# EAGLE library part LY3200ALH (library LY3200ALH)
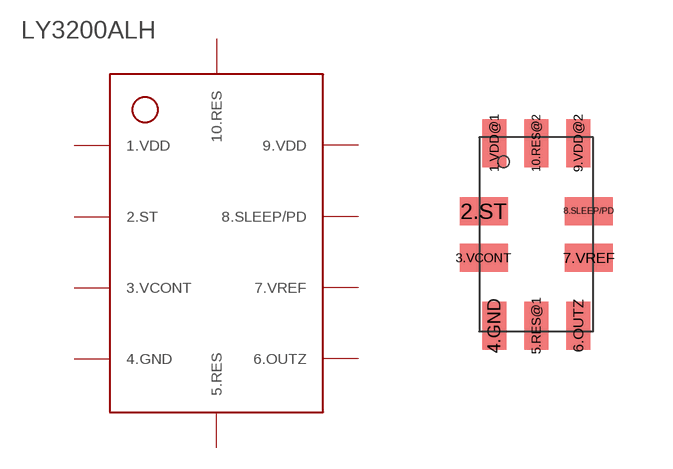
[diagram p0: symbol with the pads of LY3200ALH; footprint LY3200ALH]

Designator prefix -

## LY3200ALH  [LY3200ALH]
1.VDD@1  1.VDD
2.ST  2.ST
3.VCONT  3.VCONT
4.GND  4.GND
5.RES@1  5.RES
6.OUTZ  6.OUTZ
7.VREF  7.VREF
8.SLEEP/PD  8.SLEEP/PD
9.VDD@2  9.VDD
10.RES@2  10.RES

## Footprint LY3200ALH (pad centres in mm)
smd 0.6 x 1.2: 1.VDD@1 -1.065,2.37; 4.GND -1.065,-2.2; 5.RES@1 -0.015,-2.2; 6.OUTZ 1.035,-2.2; 9.VDD@2 1.035,2.37; 10.RES@2 -0.015,2.37
smd 1.2 x 0.7: 2.ST -1.33,0.67; 3.VCONT -1.33,-0.5; 7.VREF 1.3,-0.5; 8.SLEEP/PD 1.3,0.67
